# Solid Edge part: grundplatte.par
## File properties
Author: Wir
Template: Normal.par
Last saved by: Wir
Revision: 1
Application: Solid Edge
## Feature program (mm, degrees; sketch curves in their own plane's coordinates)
sketch for "unnamed Protrusion 1" plane through (0, 0, 0) normal (0, 0, 1) x-axis (1, 0, 0)
extrude "unnamed Protrusion 1" add finite 10 symmetric
sketch for "unnamed Cutout 1" #1 plane through (0, 0, 5) normal (0, 0, 1) x-axis (0, 1, 0)
  line (5, -50) -> (10, -50)
  line (10, -50) -> (10, -40)
  line (10, -40) -> (5, -40)
  line (5, -40) -> (5, -50)
sketch for "unnamed Cutout 1" #2 plane through (0, 0, 5) normal (0, 0, 1) x-axis (0, 1, 0)
extrude "unnamed Cutout 1" cut finite 158.75 symmetric
sketch for "unnamed Cutout 2" plane through (0, 0, 5) normal (0, 0, 1) x-axis (0, 1, 0)
  line (-2.5, 45) -> (2.5, 45)
  line (2.5, 45) -> (2.5, 55)
  line (2.5, 55) -> (-2.5, 55)
  line (-2.5, 55) -> (-2.5, 45)
extrude "unnamed Cutout 2" cut finite 114.3 symmetric
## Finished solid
Body 1: solid body, 18 faces, 48 edges, 32 vertices.
  Faces by surface: plane 18
  Edges by curve: line 48
Bounding box of the edges (mm): 150.000 x 80.000 x 10.000, from (-75, -40, -5) to (75, 40, 5).
Planar faces by outward normal: +x 4, +y 4, +z 1, -x 4, -y 4, -z 1
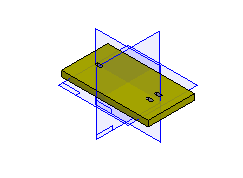
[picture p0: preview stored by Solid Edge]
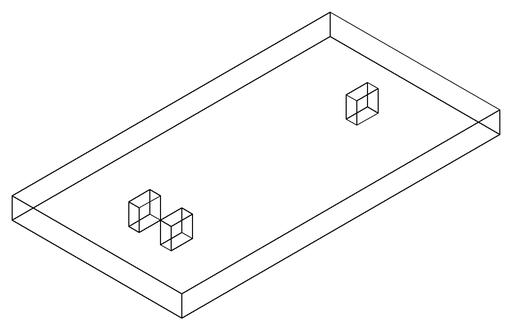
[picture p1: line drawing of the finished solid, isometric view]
